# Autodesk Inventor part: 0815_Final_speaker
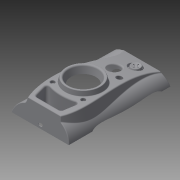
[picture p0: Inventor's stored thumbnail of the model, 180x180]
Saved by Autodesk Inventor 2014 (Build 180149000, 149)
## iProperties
Created: 2006-08
Part Number: 0815_Final_speaker
Document SubType Name: Modeling
Designer: gjie
Density: 1 g/cm^3
Material: Generic
Appearance: Default
d0: -77.809 mm
d1: 110.610 mm
d2: 113.198 mm
d4: 34.874 mm
d5: 35.763 mm
d235: 5.000 ul
d237: 22.640 mm
d238: 0.000 mm
d239: 11.320 mm
d240: 88.363 mm
d241: 33.959 mm
d242: 1.000 mm
d244: 1.00 deg
d254: 2.250 mm
d255: 11.250 mm
d256: 11.250 mm
d257: 4.704 mm
d258: 4.950 mm
d260: 0.00 deg
d202: 3.000 mm
d203: 0.500 ul
d204: 2.000 mm
d205: 0.750 ul
d206: 2.000 mm
d207: 0.250 ul
d208: 38.000 mm
d209: 0.400 mm
d210: 1.000 mm
d211: 2.884 mm
d212: 1.697 mm
d213: 15.000 mm
d214: -1.00 deg
d215: 4.000 ul
d216: 360.00 deg
d224: 0.000 mm
d226: 4.000 mm
d227: 0.000 mm
d229: 1.750 mm
d230: 6.792 mm
d231: 45.599 mm
d232: 1.000 mm
d234: 1.00 deg
d171: 5.500 mm
d172: -2.00 deg
d175: 2.264 mm
d180: 5.160 mm
d182: 2.00 deg
d183: 18.00 deg
d186: -20.000 mm
d187: 70.000 mm
d190: 1.000 mm
d191: 0.000 ul
d192: 3.000 mm
d193: 0.500 ul
d194: 2.000 mm
d195: 0.750 ul
d196: 2.000 mm
d197: 0.250 ul
d200: 1.000 mm
d201: 0.000 ul
d148: 54.676 mm
d149: 25.585 mm
d150: 4.000 mm
d151: 44.867 mm
d152: 3.000 mm
d153: 3.000 mm
d154: 1.000 mm
d155: 1.000 mm
d156: 1.000 mm
d158: 1.000 mm
d169: 1.000 mm
d143: 2.000 mm
d144: 54.100 mm
d145: 5.000 mm
d146: 1.500 mm
d147: 4.000 mm
d122: 0.00 deg
d123: 80.00 deg
d124: 35.000 mm
d125: -27.000 mm
d126: -1.500 mm
d127: 0.000 ul
d128: 90.00 deg
d129: 0.000 ul
d130: 90.00 deg
d139: 2.000 mm
d142: 2.000 mm
d94: 6.200 mm
d96: -2.00 deg
d98: 35.000 mm
d99: -22.800 mm
d101: -30.00 deg
d103: 88.795 mm
d104: 13.762 mm
d105: 25.000 mm
d107: -2.00 deg
d108: 21.000 mm
d110: -15.00 deg
d112: 5.500 mm
d117: -90.000 mm
d118: 3.396 mm
d119: 4.802 mm
d120: 3.345 mm
d74: 57.968 mm
d75: 11.320 mm
d76: -20.00 deg
d77: -26.000 mm
d78: -31.500 mm
d79: 30.000 mm
d80: 30.000 mm
d81: 8.415 mm
d83: -2.00 deg
d84: 3.000 mm
d86: -2.00 deg
d87: 23.384 mm
d88: 47.477 mm
d89: 11.698 mm
d90: -24.000 mm
d91: -15.500 mm
d93: -2.00 deg
d58: 90.00 deg
d59: 12.00 deg
d60: 1.132 mm
d61: 1.129 mm
d62: 4.851 mm
d63: 4.500 mm
d64: 2.800 mm
d65: 39.000 mm
d66: 97.000 mm
d67: 16.000 mm
d68: 32.000 mm
d69: 75.000 mm
d70: 45.279 mm
d71: 66.540 mm
d73: 15.00 deg
d39: 34.164 mm
d40: 20.000 mm
d41: 550.000 mm
d43: 47.516 mm
d44: 18.197 mm
d46: 5.500 mm
d47: 45.140 mm
d53: 90.000 mm
d54: 68.846 mm
d55: 0.000 ul
d56: 90.00 deg
d57: 0.000 ul
d29: 34.733 mm
d30: 25.039 mm
d33: 60.000 mm
d34: 54.000 mm
d36: 15.00 deg
d37: 40.201 mm
d38: 60.000 mm
d6: 25.594 mm
d7: 25.988 mm
d8: 34.637 mm
d9: 36.000 mm
d10: 29.924 mm
d11: 30.287 mm
d12: 32.540 mm
d13: 19.000 mm
d14: 21.000 mm
d15: 30.000 mm
d16: 0.000 ul
d17: 90.00 deg
d18: 0.000 ul
d19: 90.00 deg
d20: 38.000 mm
d23: 29.732 mm
d24: 32.155 mm
d25: 27.495 mm
d26: 37.131 mm
d27: 40.000 mm
d28: 42.898 mm
Author: gjie
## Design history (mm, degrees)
workplane "Work Plane1"
workplane "Work Plane2"
sketch "Sketch2"
  geometry: L1 (84.179, 0)-(-83.977, 0) reference; L2 (0, -83.776)-(0, 58.296) reference; A1 r 34.874 centre (22.705, -8.209) between (56.599, 0) and (31.282, 25.594); A2 r 35.763 centre (-21.673, -7.692) between (-33.7, 25.988) and (-56.599, 0); A3 r 95.002 centre (-1.75, -63.48) between (31.282, 25.594) and (-33.7, 25.988); 1 further point; 1 other entity
  constraints: 6 point on circle, 3 centre point, 3 point on line, 1 tangent, 4 other
  dimensions: "d2" = 113.198 distance of A1.start A2.end; "d4" = 34.874 radius of A1; "d5" = 35.763 radius of A2; "d6" = 25.594 distance from line of L1 A1.end; "d7" = 25.988 dimension on A2.start; "d8" = 34.637 distance of A2.end A2.start; "d9" = 36 distance of A1.start A1.end
sketch "Sketch3"
  geometry: L1 (83.125, 0)-(-83.178, 0) reference; L2 (0, -1501.91)-(0, 294.652) reference; L3 (56.599, 0)-(-56.599, 0) reference; A1 r 29.924 centre (-27.762, -7.991) between (-35.175, 21) and (-56.599, 0); A2 r 30.287 centre (28.474, -11.239) between (56.599, 0) and (30.182, 19); A3 r 1266.273 centre (-41.215, -1245.259) between (30.182, 19) and (-35.175, 21)
  constraints: 6 point on circle, 3 centre point, 1 tangent
  dimensions: "d10" = 29.924 radius of A1; "d11" = 30.287 radius of A2; "d12" = 32.54 distance of L3.start A2.end; "d13" = 19 distance from line of L1 A2.end; "d14" = 21 distance from line of L1 A1.start; "d15" = 30 distance of L3.end A1.start
loft "Loft1" sketch "Sketch2", "Sketch3" dims count "d16" = 0, angle "d17" = 90 deg, count "d18" = 0, angle "d19" = 90 deg
workplane "Work Plane3"
sketch "Sketch4"
  geometry: L1 (-79.239, 0)-(79.239, 0) reference; L2 (0, -118.207)-(0, 151.367) reference; L3 (-79.239, -77.809)-(79.239, -77.809) reference; L4 (56.599, 110.61)-(-56.599, 110.61) reference; 8 further points
  constraints: 4 point on line, 8 other
  dimensions: "d23" = 29.732 distance from line of L2 point (-29.732, -77.809); "d24" = 32.155 distance from line of L2 point (32.155, -77.809); "d25" = 27.495 distance from line of L2 point (-27.495, 110.61); "d26" = 37.131 distance from line of L2 point (37.131, 110.61); "d27" = 40 distance from line of L2 point (-40, -17.809); "d28" = 42.898 distance from line of L2 point (42.898, -23.809); "d29" = 34.733 distance from line of L2 point (34.733, 50.61); "d30" = 25.039 distance from line of L2 point (-25.039, 70.409); "d33" = 60 distance from line of L3 point (-40, -17.809); "d34" = 54 distance from line of L3 point (42.898, -23.809); "d37" = 40.201 distance from line of L4 point (-25.039, 70.409); "d38" = 60 distance from line of L4 point (34.733, 50.61)
extrude "Extrusion1" join sketch "Sketch4" stored distance "d35" = 10; taper "d36" = 15 deg
split "Split1"
split "Split2"
sketch "Sketch5"
  geometry: L1 (-77.809, 153.423)-(-77.809, -624.326) reference; L2 (110.61, 153.423)-(110.61, -624.326) reference; L3 (-115.615, 0)-(149.029, 0) reference; A1 r 550 centre (-24.215, -513.219) between (110.61, 20) and (-77.809, 34.164)
  constraints: 2 point on circle, 2 point on line, 1 centre point
  dimensions: "d39" = 34.164 distance from line of L3 A1.end; "d40" = 20 distance from line of L3 A1.start; "d41" = 550 radius of A1
split "Split3" sketch "Sketch5"
sketch "Sketch6"
  geometry: L1 (-33.193, 0)-(33.193, 0) reference; L2 (0, -98.911)-(0, 125.502) reference; L3 (-17.07, -65.713)-(17.07, -65.713); L4 (22.57, -60.213)-(22.57, -53.016); L5 (17.07, -47.516)-(-17.07, -47.516); L6 (-22.57, -53.016)-(-22.57, -60.213); A1 r 5.5 centre (17.07, -60.213) between (17.07, -65.713) and (22.57, -60.213); A2 r 5.5 centre (17.07, -53.016) between (22.57, -53.016) and (17.07, -47.516); A3 r 5.5 centre (-17.07, -60.213) between (-22.57, -60.213) and (-17.07, -65.713); A4 r 5.5 centre (-17.07, -53.016) between (-17.07, -47.516) and (-22.57, -53.016); 1 further point
  constraints: 8 end point, 8 point on circle, 8 tangent, 4 centre point, 3 equal radius, 2 parallel, 1 horizontal, 1 midpoint, 1 perpendicular, 1 point on line
  dimensions: "d43" = 47.516 distance between parallel lines of L1 L5; "d44" = 18.197 distance between parallel lines of L5 L3; "d46" = 5.5 radius of A1; "d47" = 45.14 distance between parallel lines of L6 L4
sketch "Sketch7"
  geometry: L1 (-45.633, 0)-(45.633, 0) reference; L2 (0, -102.123)-(0, 126.037) reference; L3 (31.239, -44.147)-(26.334, -65.732); L4 (22.433, -68.846)-(-22.433, -68.846); L5 (-26.334, -65.732)-(-31.239, -44.147); A1 r 90 centre (0, 46.676) between (-26.175, -39.434) and (26.175, -39.434); A2 r 4 centre (27.338, -43.261) between (31.239, -44.147) and (26.175, -39.434); A3 r 4 centre (-27.338, -43.261) between (-26.175, -39.434) and (-31.239, -44.147); A4 r 4 centre (22.433, -64.846) between (22.433, -68.846) and (26.334, -65.732); A5 r 4 centre (-22.433, -64.846) between (-26.334, -65.732) and (-22.433, -68.846); 3 further points
  constraints: 10 point on circle, 8 tangent, 6 end point, 5 centre point, 5 point on line, 2 equal radius, 1 perpendicular, 2 other
  dimensions: "d53" = 90 radius of A1; "d54" = 68.846 distance between parallel lines of L1 L4; "d147" = 4 radius of A2; "d148" = 54.67592 distance of A2.centre A3.centre; "d149" = 25.58531 distance from line of L4 A2.centre; "d150" = 4 radius of A4; "d151" = 44.86682 distance of L4.start L4.end
loft "Loft2" sketch "Sketch6", "Sketch7" dims count "d55" = 0, angle "d56" = 90 deg, count "d57" = 0, angle "d58" = 90 deg
feature "FaceDraft3" dims angle "d59" = 12 deg
workplane "Work Plane4"
sketch "Sketch9"
  geometry: L1 (-46.578, 0)-(46.578, 0) reference; L2 (0, -58.613)-(0, 118.786) reference; C1 r 33.27 at (0, 0)
  constraints: 1 centre point, 1 midpoint, 1 point on line
  dimensions: "d71" = 66.54 diameter of C1
extrude "Extrusion3" join sketch "Sketch9" stored distance "d72" = 10; taper "d73" = 15 deg
sketch "Sketch10"
  geometry: L1 (-40.578, 0)-(40.578, 0) reference; L2 (0, -53.469)-(0, 117.928) reference; C1 r 28.984 at (0, 0)
  constraints: 1 centre point, 1 midpoint, 1 point on line
  dimensions: "d74" = 57.968 diameter of C1
extrude "Extrusion4" cut sketch "Sketch10" distance "d75" = 11.32; taper "d76" = -20 deg
workplane "Work Plane5"
workplane "Work Plane6"
sketch "Sketch11"
  geometry: L1 (-44.577, 0)-(28.01, 0) reference; L2 (0, -59.738)-(0, 118.973) reference; C1 r 4.207 at (-30, -30)
  constraints: 1 centre point
  dimensions: "d79" = 30 distance from line of L2 C1.centre; "d80" = 30 distance from line of L1 C1.centre; "d81" = 8.415 diameter of C1
extrude "Extrusion5" cut sketch "Sketch11" stored distance "d82" = 9.872; taper "d83" = -2 deg
sketch "Sketch12"
  geometry: C1 r 3.726 at (-30, -30) reference; C2 r 1.5 at (-30, -30)
  constraints: 1 centre point, 1 coincident
  dimensions: "d84" = 3 diameter of C2
extrude "Extrusion6" cut sketch "Sketch12" stored distance "d85" = 9.872; taper "d86" = -2 deg
workplane "Work Plane7"
workplane "Work Plane8"
sketch "Sketch13"
  geometry: L1 (6.878, 0)-(32.959, 0) reference; L2 (0, 31.265)-(0, 103.806) reference; C1 r 5.849 at (23.384, 47.477)
  constraints: 1 centre point
  dimensions: "d87" = 23.384 distance from line of L2 C1.centre; "d88" = 47.477 distance from line of L1 C1.centre; "d89" = 11.698 diameter of C1
extrude "Extrusion7" cut sketch "Sketch13" stored distance "d92" = 9.872; taper "d93" = -2 deg
sketch "Sketch14"
  geometry: C1 r 5.106 at (23.384, 47.477) reference; C2 r 3.1 at (23.384, 47.477)
  constraints: 1 centre point, 1 coincident
  dimensions: "d94" = 6.2 diameter of C2
extrude "Extrusion8" cut sketch "Sketch14" stored distance "d95" = 9.872; taper "d96" = -2 deg
workplane "Work Plane16"
  workplane "Work Plane15"
sketch "Sketch15"
  geometry: L1 (-79.379, 0)-(79.379, 0) reference; L2 (0, 121.953)-(0, -164.488) reference; C1 r 17.5 at (0, -70)
  constraints: 1 centre point, 1 point on line
  dimensions: "d98" = 35 diameter of C1; "d187" = 70 distance from line of L1 C1.centre
extrude "Extrusion9" cut sketch "Sketch15" stored distance "d100" = 1; taper "d101" = -30 deg
workplane "Work Plane10"
  workplane "Work Plane13"
sketch "Sketch16"
  geometry: L1 (-3.738, 0)-(31.262, 0) reference; L2 (0, 71.295)-(0, 106.295) reference; C1 r 12.5 at (13.762, 88.795)
  constraints: 1 centre point
  dimensions: "d103" = 88.795 distance from line of L1 C1.centre; "d104" = 13.762 distance from line of L2 C1.centre; "d105" = 25 diameter of C1
extrude "Extrusion10" cut sketch "Sketch16" stored distance "d106" = 1; taper "d107" = -2 deg
workplane "Work Plane14"
sketch "Sketch17"
  geometry: C1 r 11.575 at (0, 0); C2 r 10.5 at (0, 0); 1 further point; 1 other entity
  constraints: 2 centre point, 1 coincident, 2 other
  dimensions: "d108" = 21 diameter of C2
extrude "Extrusion11" join sketch "Sketch17" stored distance "d109" = 6.5; taper "d110" = -15 deg
workplane "Work Plane11"
sketch "Sketch18"
  geometry: C1 r 2.75 at (0, 0); 1 further point; 1 other entity
  constraints: 1 centre point, 2 other
  dimensions: "d112" = 5.5 diameter of C1
loft "Loft4" sketch "Sketch18" dims count "d127" = 0, angle "d128" = 90 deg, count "d129" = 0, angle "d130" = 90 deg
  node "Edges2"
fillet "Fillet2" dims "d139" = 2
fillet "Fillet5" dims "d142" = 2
fillet "Fillet6" dims "d143" = 2
fillet "Fillet7" dims "d144" = 54.1
fillet "Fillet8" dims "d145" = 5
fillet "Fillet9" dims "d146" = 1.5
fillet "Fillet10" dims "d152" = 3
fillet "Fillet11" dims "d153" = 3
fillet "Fillet12" dims "d154" = 1
fillet "Fillet13" dims "d155" = 1
fillet "Fillet14" dims "d156" = 1
fillet "Fillet16" dims "d158" = 1
mirror "Mirror2"
fillet "Fillet18" dims "d169" = 1
fillet "Fillet19" dims "d188" = 7, "d189" = 7, "d190" = 1, count "d191" = 0, "d192" = 3, count "d193" = 0.5, "d194" = 2, count "d195" = 0.75, "d196" = 2, count "d197" = 0.25
shell "Shell2" dims "d60" = 1.132, "d61" = 1.129
sketch "Sketch20"
  geometry: C1 r 2.761 at (0, 0) reference
extrude "Extrusion13" join sketch "Sketch20" distance "d171" = 5.5; taper "d172" = -2 deg
hole "Hole1" diameter "d175" = 2.264; stored, may be unused: countersink angle "d179" = 90 deg, drill point angle "d181" = 0 deg; dims "d173" = 10, "d174" = 10, "d176" = 6, "d177" = 4, "d178" = 2, "d180" = 5.16
feature "FaceDraft4" dims angle "d182" = 2 deg
workplane "Work Plane12"
sketch "Sketch19"
  geometry: L1 (8.447, 0)-(-21.989, 0) reference; L2 (0, -3.586)-(0, 44.931) reference; L3 (1.698, 8.147)-(-1.698, 8.147); L4 (-1.698, 3.345)-(1.698, 3.345); A1 r 2.401 centre (-1.698, 5.746) between (-1.698, 8.147) and (-1.698, 3.345); A2 r 2.401 centre (1.698, 5.746) between (1.698, 3.345) and (1.698, 8.147); 1 further point
  constraints: 4 end point, 4 point on circle, 3 tangent, 2 centre point, 2 perpendicular, 1 equal radius, 1 midpoint, 1 point on line
  dimensions: "d118" = 3.396 distance of L3.start L3.end; "d119" = 4.802 distance between parallel lines of L4 L3; "d120" = 3.345 distance between parallel lines of L1 L4
extrude "Extrusion12" cut sketch "Sketch19" stored distance "d121" = 7; taper "d122" = 0 deg
fillet "Fillet20" dims "d198" = 5, "d199" = 5, "d200" = 1, count "d201" = 0, "d202" = 3, count "d203" = 0.5, "d204" = 2, count "d205" = 0.75, "d206" = 2, count "d207" = 0.25
workplane "Work Plane17"
sketch "Sketch21"
  geometry: L1 (21.978, 89.564)-(3.543, 89.564); L2 (13.762, 77.734)-(13.762, 99.906); L3 (12.146, 89.173)-(9.323, 88.585); L4 (12.146, 89.956)-(9.323, 90.543); C1 r 2.75 at (13.762, 89.564) reference; A1 r 0.4 centre (12.065, 89.564) between (12.146, 89.173) and (12.146, 89.956); A2 r 1 centre (9.119, 89.564) between (9.323, 90.543) and (9.323, 88.585)
  constraints: 8 end point, 4 point on circle, 4 point on line, 4 tangent, 2 centre point, 1 horizontal, 1 perpendicular
  dimensions: "d209" = 0.4 radius of A1; "d210" = 1 radius of A2; "d211" = 2.884 distance of L3.start L3.end; "d212" = 1.697 distance of C1.centre A1.centre
extrude "Extrusion14" cut sketch "Sketch21" distance "d213" = 15; taper "d214" = -1 deg
sketch "Sketch28"
  geometry: L1 (12.102, 89.386)-(11.041, 89.166) reference; L2 (11.041, 89.963)-(12.102, 89.742) reference; A1 r 2.75 centre (13.762, 89.564) between (11.041, 89.166) and (13.762, 86.814) reference; A2 r 2.75 centre (13.762, 89.564) between (13.762, 86.814) and (11.041, 89.963) reference; A3 r 0.182 centre (12.065, 89.564) between (12.102, 89.386) and (12.102, 89.742) reference
  node "Projected Loop1"
workpoint "Work Point1"
workaxis "Work Axis1"
pattern_circular "Circular Pattern1" dims count "d215" = 4, angle "d216" = 360 deg
feature "OffsetSrf1" dims "d224" = 0, "d225" = 0
feature "Extend1" dims "d226" = 4
feature "Sculpt1"
feature "OffsetSrf2" dims "d227" = 0, "d228" = 0
feature "Extend2" dims "d229" = 1.75
feature "Sculpt2"
sketch "Sketch24"
  geometry: L1 (55.11, 113.704)-(-55.059, 113.704) reference; L2 (45.599, 106.912)-(45.599, 113.704); L3 (0, 80.829)-(0, 119.183) reference
  constraints: 2 end point, 1 perpendicular, 1 point on line
  dimensions: "d230" = 6.792 distance of L2.start L2.end; "d231" = 45.599 distance between parallel lines of L3 L2
feature "Rib1" sketch "Sketch24" dims "d232" = 1, "d233" = 1, angle "d234" = 1 deg
pattern_linear "Rectangular Pattern1" dims count "d235" = 5, "d237" = 22.64
workplane "Work Plane18"
sketch "Sketch25"
  geometry: L1 (-57.863, 0)-(30.225, 0) reference; L2 (0, 84.881)-(0, 94.87) reference; L3 (-33.959, 88.363)-(-45.279, 88.363)
  constraints: 2 end point, 1 perpendicular
  dimensions: "d239" = 11.32 distance of L3.start L3.end; "d240" = 88.363 distance between parallel lines of L1 L3; "d241" = 33.959 distance from line of L2 L3.start
feature "Rib2" sketch "Sketch25" dims "d242" = 1, "d243" = 1, angle "d244" = 1 deg
mirror "Mirror3"
sketch "Sketch8"
  geometry: L1 (-68.106, 0)-(126.117, 0) reference; L2 (0, -8.025)-(0, 45.671) reference; 5 further points
  constraints: 2 point on line, 5 other
  dimensions: "d62" = 4.851 distance from line of L1 point (-16, 4.851); "d63" = 4.5 distance from line of L1 point (75, 4.5); "d64" = 2.8 distance from line of L1 point (32, 2.8); "d65" = 39 distance from line of L2 point (-39, 0); "d66" = 97 distance from line of L2 point (97, 0); "d67" = 16 distance from line of L2 point (-16, 4.851); "d68" = 32 distance from line of L2 point (32, 2.8); "d69" = 75 distance from line of L2 point (75, 4.5)
split "Split4" sketch "Sketch8"
workplane "Work Plane19"
sketch "Sketch27"
  geometry: L1 (-58.289, 23.64)-(101.597, 23.64) reference; L2 (21.64, 0)-(0, 0) reference; L3 (16.871, 4.704)-(5.621, 4.704); L4 (5.621, 4.704)-(5.621, 15.954); L5 (5.621, 15.954)-(16.871, 15.954); L6 (16.871, 15.954)-(16.871, 4.704); L7 (21.821, -22.483)-(21.821, 105.73) reference
  constraints: 8 end point, 2 parallel, 1 horizontal, 1 perpendicular
  dimensions: "d255" = 11.25 distance of L3.start L3.end; "d256" = 11.25 distance of L3.end L4.end (derived); "d257" = 4.704 distance between parallel lines of L2 L3; "d258" = 4.95 distance between parallel lines of L7 L6
extrude "Extrusion16" join sketch "Sketch27" stored distance "d259" = 3; taper "d260" = 0 deg
body "Solid1"
workplane "Work Plane9"
body "Srf1"
body "Srf2"
other parameters: "d0" = -77.809, "d1" = 110.61, "d20" = 38, "d70" = 45.279, "d77" = -26, "d78" = -31.5, "d90" = -24, "d91" = -15.5, "d99" = -22.8, "d117" = -90, "d123" = 80 deg, "d124" = 35, "d125" = -27, "d126" = -1.5, "d183" = 18 deg, "d186" = -20, "d208" = 38, "d238" = 0, "d254" = 2.25
